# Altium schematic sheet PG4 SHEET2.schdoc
size B; Date: 2/10/2009; ApprovedBy: Touraj; DrawnBy: Juan A. Nadal; Engineer: Touraj; Organization: ActiveWave; Address1: 902 Clint Moore Rd., Suite 118; Address2: Boca Raton; Address3: FL, 33487; Address4: 561-999-9422; DocumentNumber: 4; Revision: 18; SheetNumber: 4; SheetTotal: 4; PageSetup: Record=PageOptions|CenterHorizontal=True|CenterVertical=True|PrintScale=0.70|XCorrection=1.00|YCorrection=1.00|PrintKind=0|BorderSize=5000000|LeftOffset=0|BottomOffset=0|Orientation=2|PaperLength=1000|PaperWidth=1000|Scale=100|PaperSource=7|PrintQuality=-4|MediaType=1|DitherType=10|PaperKind=Letter|PrintScaleMode=1; Project: Tag105
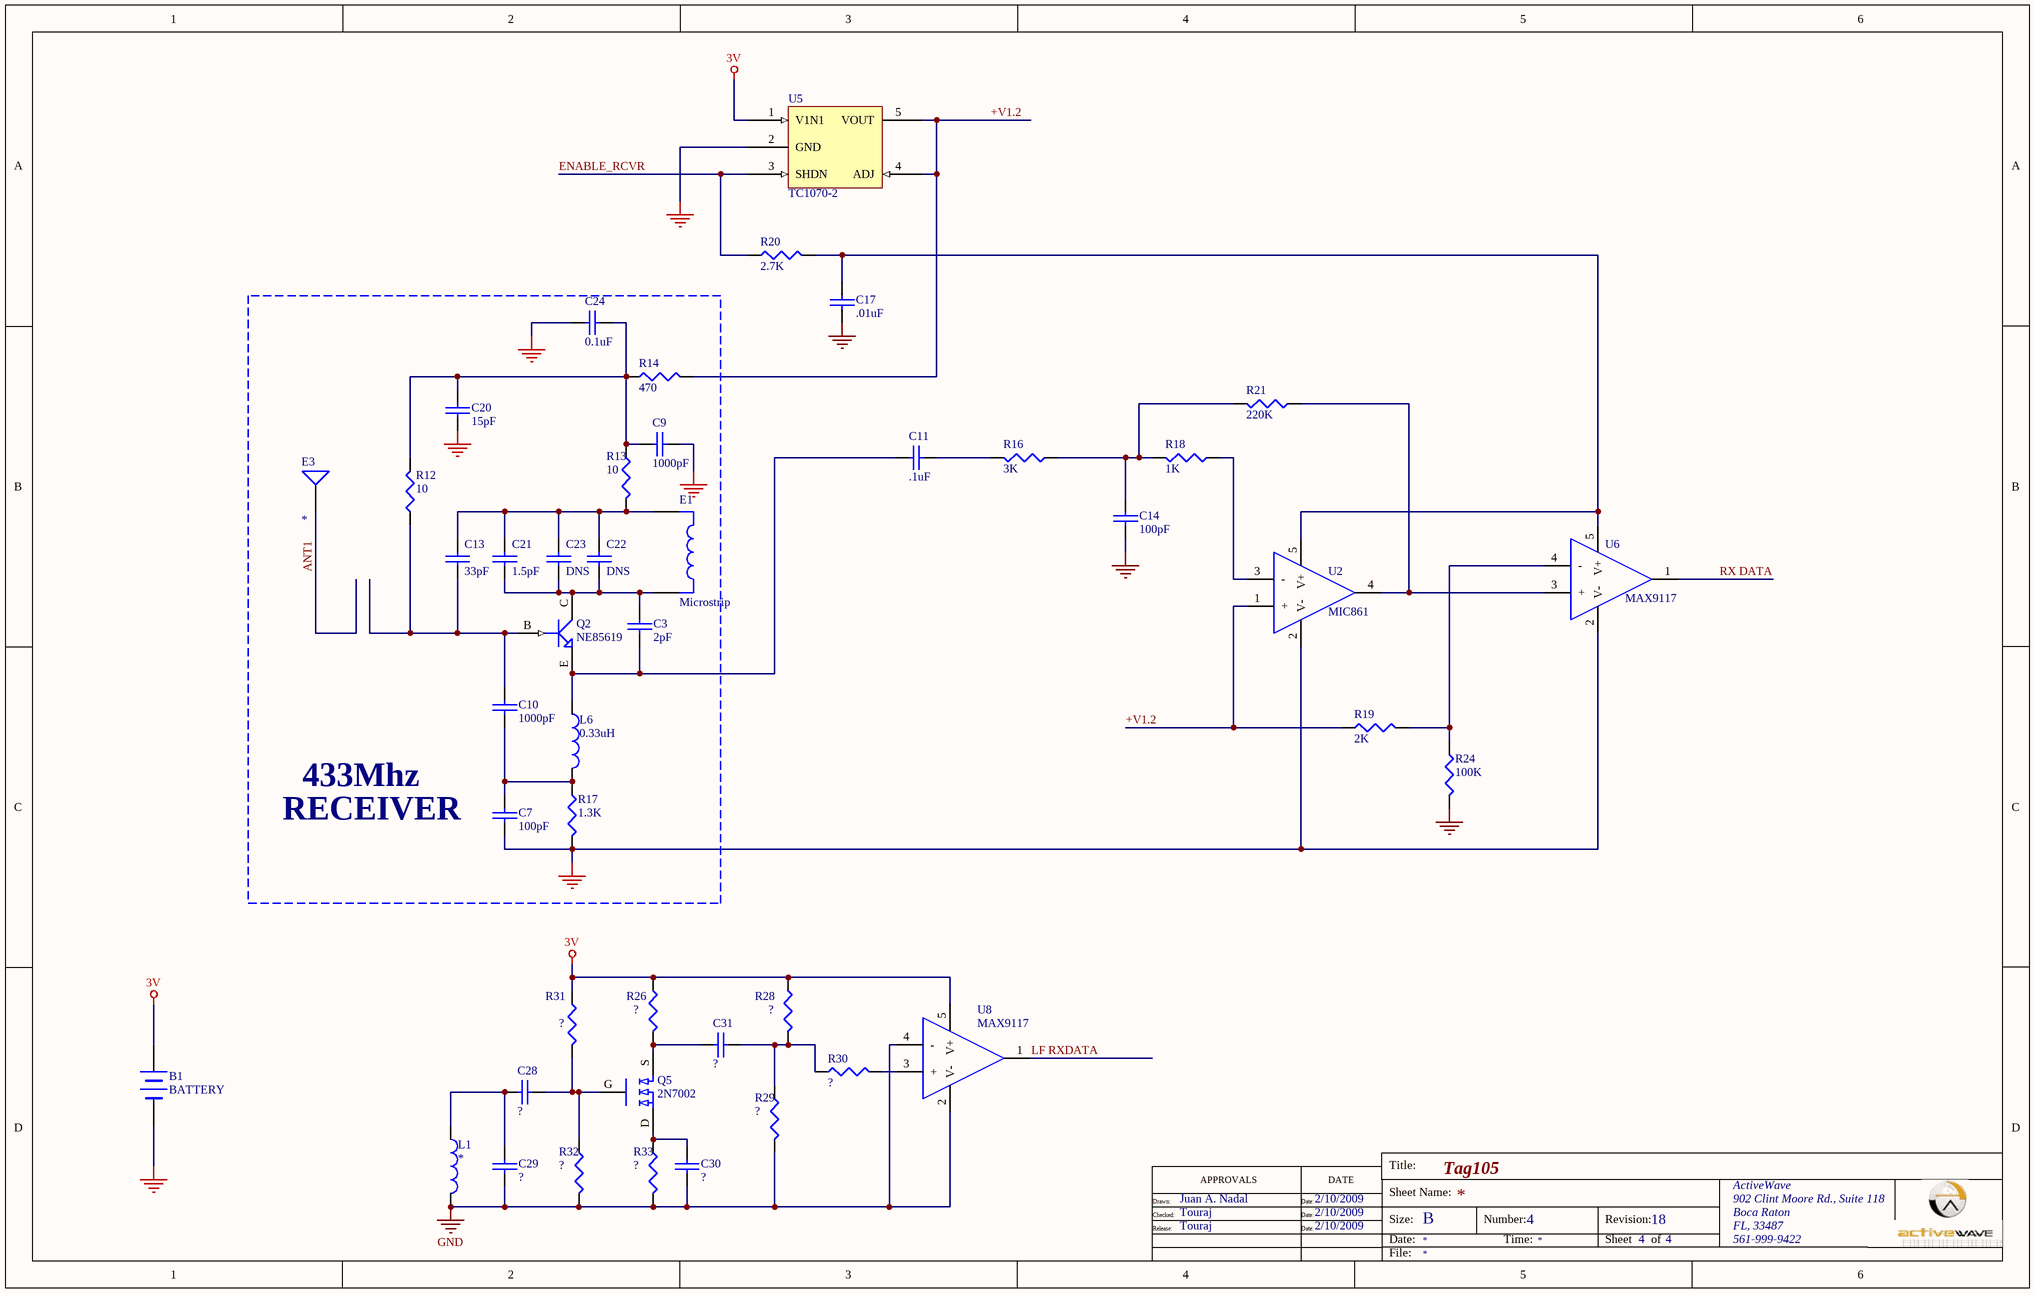
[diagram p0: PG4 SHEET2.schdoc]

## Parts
B1  BATTERY  [BATT HOLDER COIN CR2032 CUT]
C3  2pF  [0603]
C7  100pF  [0603]
C9  1000pF  [0603]
C10  1000pF  [0603]
C11  .1uF  [0603]
C13  33pF  [0603]
C14  100pF  [0603]
C17  .01uF  [0603]
C20  15pF  [0603]
C21  1.5pF  [0603]
C22  DNS  [0603]
C23  DNS  [0603]
C24  0.1uF  [0603]
C28  ?  [0603]
C29  ?  [0603]
C30  ?  [0603]
C31  ?  [0603]
E1  Microstrip  [Antenna]  (net tie, no BOM)
E3  *  [Antenna1]
L1  *  [4308RV]
L6  0.33uH  [0603]
Q2  NE85619  [3 PIN ULTRA SUPER MINI MOLD]
Q5  2N7002  [SOT23 FET]
R12  10  [0603]
R13  10  [0603]
R14  470  [0603]
R16  3K  [0603]
R17  1.3K  [0603]
R18  1K  [0603]
R19  2K  [0603]
R20  2.7K  [0603]
R21  220K  [0603]
R24  100K  [0603]
R26  ?  [0603]
R28  ?  [0603]
R29  ?  [0603]
R30  ?  [0603]
R31  ?  [0603]
R32  ?  [0603]
R33  ?  [0603]
U2  MIC861  [SC70]
U5  TC1070-2  [SOT23-5A]
U6  MAX9117  [SC70]
U8  MAX9117  [SC70]

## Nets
3V: B1.2(+) R26.1 R28.1 R31.1 U5.1(V1N1) U8.5(V+)
GND: B1.1(-) C7.2 C9.2 C14.1 C17.2 C20.2 C24.2 C29.1 C30.1 L1.2 R17.2 R24.2 R29.2 R32.2 R33.2 U2.2(V-) U5.2(GND) U6.2(V-) U8.2(V-) U8.4(-)
+V1.2: R14.2 R19.1 U2.1(+) U5.4(ADJ) U5.5(VOUT)
ANT1: E3.1
ENABLE_RCVR: R20.1 U5.3(SHDN)
LF RXDATA: U8.1(OUT)
RX DATA: U6.1(OUT)
NetC3_1: C3.1 C21.2 C22.2 C23.2 E1.1 Q2.C
NetC3_2: C3.2 C11.1 L6.1 Q2.E
NetC7_1: C7.1 C10.2 L6.2 R17.1
NetC9_1: C9.1 C20.1 C24.1 R12.2 R13.1 R14.1
NetC10_1: C10.1 C13.2 Q2.B R12.1
NetC11_2: C11.2 R16.2
NetC13_1: C13.1 C21.1 C22.1 C23.1 E1.2 R13.2
NetC14_2: C14.2 R16.1 R18.2 R21.2
NetC17_1: C17.1 R20.2 U2.5(V+) U6.5(V+)
NetC28_1: C28.1 C29.2 L1.1
NetC28_2: C28.2 Q5.G R31.2 R32.1
NetC30_2: C30.2 Q5.D R33.1
NetC31_1: C31.1 Q5.S R26.2
NetC31_2: C31.2 R28.2 R29.1 R30.1
NetR18_1: R18.1 U2.3(-)
NetR19_2: R19.2 R24.1 U6.4(-)
NetR21_1: R21.1 U2.4(OUT) U6.3(+)
NetR30_2: R30.2 U8.3(+)

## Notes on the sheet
- RECEIVER
- 433Mhz

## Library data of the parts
C3 C7 C9-C11 C13 C14 C17 C20-C24 C28-C31 = CAP-0603: Capacitor
E1 = ANTENNA
E3 = Antenna1
L1 = INDUCTOR_V1
L6 = INDUCTOR
Q2 = NE85619: TRANSISTOR NPN 1GHZ SMD; MANUFACTURER: ??????
Q5 = 2N7002: N-CHANNEL ENHANCEMENT MODE FIELD EFFECT TRANSISTOR; MANUFACTURER: FAIRCHILD
R12-R14 R16-R21 R24 R26 R28-R33 = RES-0603
U2 = MIC861BC5: Ultra Low Power Op Amp; MANUFACTURER: MICREL
U5 = TC1070-2: Adjustable CMOS LDOs with Shutdown; MANUFACTURER: Microchip Technology; ITEM-DESCRIPTION: 50mA, 100mA and 150mA Adjustable CMOS LDOs with Shutdown; MFGR-P/N: TC1070
U6 U8 = COMPARATOR MAX9117: MAX9117 Comparators; MANUFACTURER: MAXIM; ITEM-DESCRIPTION: SC70, 1.6V, Nanopower, Beyond-the-Rails Comparators With/Without Reference; MFGR-P/N: ??????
